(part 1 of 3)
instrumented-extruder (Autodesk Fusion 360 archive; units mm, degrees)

design "AS_Glue-Gun" references "AS_Hotend-Filsense", "AS_Hotend-Extruder", "AS_Hotend-Circuits", "AS_Hotend-Loadcell-Nozzle", "AS_Tool-Blank"
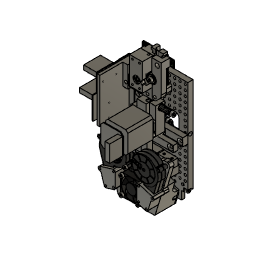
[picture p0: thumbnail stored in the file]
component_insert "Component Insert1"
joint "Assemble1" alignAngle 0 alignOffsetX 0 alignOffsetY 0 alignOffsetZ 0
component_insert "Component Insert2"
joint "Assemble2" alignAngle 0 alignOffsetX 0 alignOffsetY 0 alignOffsetZ 0
component_insert "Component Insert4"
joint "Assemble3" alignAngle 0 alignOffsetX 0 alignOffsetY 0 alignOffsetZ 0
component_insert "Component Insert13"
joint "Assemble6" alignAngle 0 alignOffsetX 0 alignOffsetY 0 alignOffsetZ 0
component_insert "Component Insert16"
joint "Assemble7" alignAngle -90 alignOffsetX 0 alignOffsetY 0 alignOffsetZ 0
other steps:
joint_origin "JointOrigin1"

design "PP_TRNS_Bondtech-Mini-Gears"
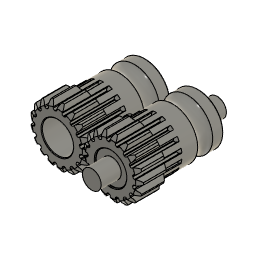
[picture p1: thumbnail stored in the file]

design "HW_M4x16-SHCS"
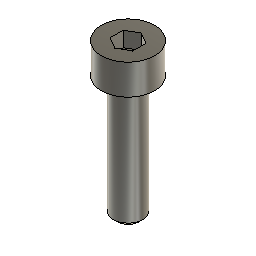
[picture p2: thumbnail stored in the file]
sketch "Sketch1" plane through (0, 0, 0) normal (0, 1, 0) x axis (1, 0, 0)
  line L1 (0, 16) -> (0, -4)
  line L2 (1.45, 16) -> (0, 16)
  line L3 (1.95, 15.5) -> (1.45, 16)
  line L4 (1.95, 0) -> (1.95, 15.5)
  line L5 (3.5, 0) -> (1.95, 0)
  line L6 (3.5, -4) -> (3.5, 0)
  line L7 (0, -4) -> (3.5, -4)
  point P1 (0, 0)
  point P4 (1.45, 16)
  point P5 (1.95, 15.5)
  point P3 (0, 16)
  point P7 (3.5, 0)
  point P8 (3.5, -4)
  point P2 (0, -4)
  vertical L1
  perpendicular L1 L2
  perpendicular L2 L4
  perpendicular L4 L5
  perpendicular L5 L6
  horizontal L7
  coincident P1 L1
  coincident P1 L5
  dimension "d1" distance P1 L2 = 16
  dimension "d2" angle L2 L3 = 45
  dimension "d3" distance P4 P5 = 0.5
  dimension "d4" distance P3 L4 = 1.95 (= "( 3.9 / 2 ) * 1 mm")
  dimension "d5" distance P7 P8 = 4
  dimension "d6" distance P2 P8 = 3.5 (= "( 7 / 2 ) * 1 mm")
revolve "Revolve1" sketch "Sketch1" AlongAngle 360
sketch "Sketch2" plane through (0, 0, 4) normal (0, 0, 1) x axis (-1, 0, 0)
  line L1 (0, -1.7321) -> (-1.5, -0.866)
  line L2 (1.5, -0.866) -> (0, -1.7321)
  line L3 (1.5, 0.866) -> (1.5, -0.866)
  line L4 (0, 1.7321) -> (1.5, 0.866)
  line L5 (-1.5, 0.866) -> (0, 1.7321)
  line L6 (-1.5, -0.866) -> (-1.5, 0.866)
  circle C1 centre (0, 0) radius 3.5
  point P1 (0, 0)
  point P9 (0, 0)
  point P5 (1.5, -0.866)
  coincident P1 P9
  vertical L6
  dimension "d8" distance P5 L6 = 3
extrude "Extrude1" cut sketch "Sketch2" profile of L1 L2 L3 L4 L5 L6 against normal blind 2

design "PP_OUTP_Dragon-Hotend"
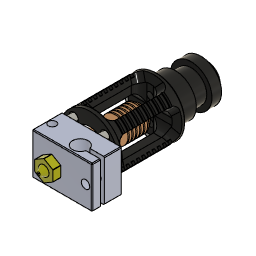
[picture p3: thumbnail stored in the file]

design "HW_M5x40-FHCS"
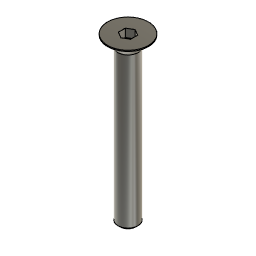
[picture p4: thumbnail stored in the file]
sketch "Sketch1" plane through (0, 0, 0) normal (0, 1, 0) x axis (1, 0, 0)
  line L1 (0, 40) -> (0, 0)
  line L2 (1.95, 40) -> (0, 40)
  line L3 (2.45, 39.5) -> (1.95, 40)
  line L4 (2.45, 2.8) -> (2.45, 39.5)
  line L5 (5, 0.25) -> (2.45, 2.8)
  line L6 (5, 0) -> (5, 0.25)
  line L7 (0, 0) -> (5, 0)
  point P1 (0, 0)
  point P2 (0, 0)
  point P9 (0, 0)
  point P3 (0, 40)
  point P4 (1.95, 40)
  point P8 (5, 0)
  point P7 (5, 0.25)
  coincident P1 P2
  vertical L1
  perpendicular L1 L2
  perpendicular L2 L4
  parallel L3 L5
  parallel L4 L6
  perpendicular L6 L7
  coincident P1 P9
  dimension "d1" distance P3 L4 = 2.45 (= "( 4.9 / 2 ) * 1 mm")
  dimension "d3" angle L2 L3 = 45
  dimension "d5" distance P4 L4 = 0.5
  dimension "d6" distance P2 P3 = 40
  dimension "d7" distance P8 P9 = 5 (= "( 10 / 2 ) * 1 mm")
  dimension "d9" distance P7 P8 = 0.25
revolve "Revolve1" sketch "Sketch1" AlongAngle 360
sketch "Sketch2" plane through (0, 0, 0) normal (0, 0, 1) x axis (-1, 0, 0)
  line L1 (0, -1.7321) -> (-1.5, -0.866)
  line L2 (1.5, -0.866) -> (0, -1.7321)
  line L3 (1.5, 0.866) -> (1.5, -0.866)
  line L4 (0, 1.7321) -> (1.5, 0.866)
  line L5 (-1.5, 0.866) -> (0, 1.7321)
  line L6 (-1.5, -0.866) -> (-1.5, 0.866)
  circle C1 centre (0, 0) radius 5
  point P1 (0, 0)
  point P9 (0, 0)
  coincident P1 P9
  vertical L6
  dimension "d12" distance L3 L6 = 3
extrude "Extrude1" cut sketch "Sketch2" profile of L1 L2 L3 L4 L5 L6 against normal blind 2

design "PP_ACTU_N17-Stepper" references "Fab Step"
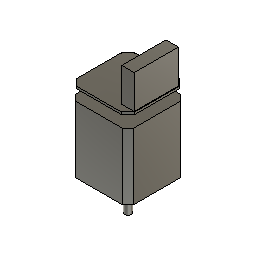
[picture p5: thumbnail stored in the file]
description: Nema 17 Stepper, 48mm Length Preferred, 5mm Shaft
sketch "Sketch1" plane through (0, 0, 0) normal (0, 0, 1) x axis (1, 0, 0)
  line L1 (-21.15, 21.15) -> (21.15, 21.15)
  line L2 (-21.15, -21.15) -> (-21.15, 21.15)
  line L3 (21.15, -21.15) -> (-21.15, -21.15)
  line L4 (21.15, 21.15) -> (21.15, -21.15)
  line L5 (-21.15, -21.15) -> (21.15, 21.15)
  line L6 (21.15, -21.15) -> (-21.15, 21.15)
  line L7 (15.5, 15.5) -> (-15.5, 15.5)
  line L8 (15.5, -15.5) -> (15.5, 15.5)
  line L9 (-15.5, -15.5) -> (15.5, -15.5)
  line L10 (-15.5, 15.5) -> (-15.5, -15.5)
  circle C1 centre (0, 0) radius 11
  circle C2 centre (-15.5, 15.5) radius 1.5
  circle C3 centre (-15.5, -15.5) radius 1.5
  circle C4 centre (15.5, -15.5) radius 1.5
  circle C5 centre (15.5, 15.5) radius 1.5
  circle C6 centre (0, 0) radius 2.5
  point P6 (0, 0)
  point P1 (0, 0)
  point P7 (0, 0)
  point P10 (15.5, -15.5)
  point P8 (-15.5, 15.5)
  point P9 (15.5, 15.5)
  point P12 (-15.5, 15.5)
  point P11 (-15.5, -15.5)
  point P13 (-15.5, -15.5)
  point P14 (15.5, -15.5)
  point P15 (15.5, 15.5)
  point P2 (21.15, 21.15)
  point P3 (-21.15, 21.15)
  perpendicular L1 L2
  parallel L1 L3
  parallel L2 L4
  horizontal L1
  coincident L5 P6
  coincident L6 P6
  coincident P1 P6
  equal L1 L2
  coincident P6 P7
  horizontal L7
  vertical L8
  horizontal L9
  vertical L10
  coincident L6 P10
  coincident L6 P8
  coincident L5 P9
  coincident P8 P12
  coincident P11 P13
  coincident P10 P14
  coincident P9 P15
  equal C2 C5
  equal C2 C3
  equal C2 C4
  concentric C1 C6
  dimension "d1" distance P2 P3 = 42.3
  dimension "d2" diameter C1 = 22
  dimension "d3" distance P8 P9 = 31
  dimension "d4" diameter C2 = 3
  dimension "d5" diameter C6 = 5
extrude "Extrude1" new body sketch "Sketch1" profile of L1 L2 L3 L4 C1 C2 C3 C4 C5 C6 along normal blind 48
extrude "Extrude2" cut sketch "Sketch1" profile of C2 C3 C4 C5 along normal blind 5
extrude "Extrude3" add sketch "Sketch1" profile of C1 C6 against normal blind 2
extrude "Extrude4" add sketch "Sketch1" profile of C6 against normal blind 24
chamfer "Chamfer1" distance 4
component_insert "Component Insert"
joint "Assemble1" alignAngle 0 alignOffsetX 0 alignOffsetY 0 alignOffsetZ 8
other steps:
joint_origin "JointOrigin1"

design "PP_FANS_40mm"
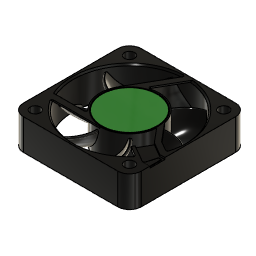
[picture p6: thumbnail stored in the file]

design "AS_Hotend-Filsense-Shaft" references "PP_BRNG_625-5x16x5", "PP_MAGU_2p5x8-469-1076-ND", "PP_SHFT_5x28-91585A562", "PP_TRNS_Bondtech-Single"
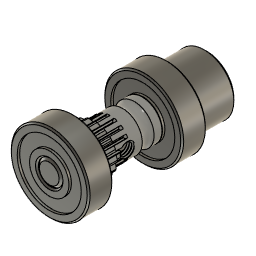
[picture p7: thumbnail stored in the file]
component_insert "Component Insert1"
component_insert "Component Insert3"
component_insert "Component Insert4"
component_insert "Component Insert5"
joint "Assemble1" alignAngle 0 alignOffsetX 0 alignOffsetY 0 alignOffsetZ 0
joint "Assemble2" alignAngle 0 alignOffsetX 0 alignOffsetY 0 alignOffsetZ 0
joint "Assemble3" alignAngle 0 alignOffsetX 0 alignOffsetY 0 alignOffsetZ 0
joint "Assemble4" alignAngle 0 alignOffsetX 0 alignOffsetY 0 alignOffsetZ 0
sketch "Sketch1" plane through (0, 0, 0) normal (1, 0, 0) x axis (0, 1, 0)
  line L1 (24, 2.45) -> (24, 6)
  line L2 (28, 2.45) -> (24, 2.45)
  line L3 (28, 0) -> (28, 2.45)
  line L4 (29.5, 0) -> (28, 0)
  line L5 (29.5, 4) -> (29.5, 0)
  line L6 (32, 4) -> (29.5, 4)
  line L7 (32, 6) -> (32, 4)
  line L8 (24, 6) -> (32, 6)
  point P2 (24, 6)
  point P10 (24, 6)
  point P1 (0, 0)
  point P4 (28, 2.45)
  point P5 (28, 0)
  point P3 (24, 2.45)
  point P6 (29.5, 0)
  point P7 (29.5, 4)
  point P8 (32, 4)
  vertical L1
  perpendicular L1 L2
  perpendicular L2 L3
  perpendicular L3 L4
  perpendicular L4 L5
  perpendicular L5 L6
  perpendicular L6 L7
  perpendicular L7 L8
  coincident P2 P10
  coincident P1 L4
  dimension "d17" distance P4 P5 = 2.45
  dimension "d18" distance P1 L3 = 28
  dimension "d19" distance P3 P4 = 4
  dimension "d20" distance P5 P6 = 1.5
  dimension "d21" distance P6 L6 = 4 (= "( 8 / 2 ) * 1 mm")
  dimension "d22" distance P7 P8 = 2.5
  dimension "d23" distance P6 L8 = 6
revolve "Revolve1" sketch "Sketch1" AlongAngle 360 bodies "FilsenseMagHold"
chamfer "Chamfer1" distance 0.5
chamfer "Chamfer2" distance 0.4
component_insert "Component Insert7"
joint "Assemble6" alignAngle 0 alignOffsetX 0 alignOffsetY 0 alignOffsetZ 0
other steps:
joint_origin "JointOrigin1"
joint_origin "JointOrigin3"
named bodies: "FilsenseMagHold"

design "HW_M5x08-BHCS"
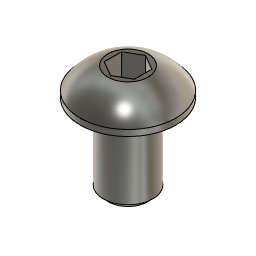
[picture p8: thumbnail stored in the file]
sketch "Sketch1" plane through (0, 0, 0) normal (0, 1, 0) x axis (1, 0, 0)
  line L1 (0, 8) -> (0, -2.75)
  line L2 (1.95, 8) -> (0, 8)
  line L3 (2.45, 7.5) -> (1.95, 8)
  line L4 (2.45, 0) -> (2.45, 7.5)
  line L5 (4.75, 0) -> (2.45, 0)
  line L6 (4.75, -0.6) -> (4.75, 0)
  line L7 (2, -2.75) -> (0, -2.75)
  arc A1 centre (0, 2.6419) radius 5.7508 clockwise from (4.75, -0.6) to (2, -2.75)
  point P1 (0, 0)
  point P10 (0, 2.6419)
  point P3 (0, 8)
  point P2 (0, -2.75)
  point P9 (2, -2.75)
  point P7 (4.75, 0)
  point P8 (4.75, -0.6)
  point P5 (2.45, 7.5)
  vertical L1
  perpendicular L1 L2
  perpendicular L2 L4
  perpendicular L4 L5
  perpendicular L5 L6
  perpendicular L1 L7
  coincident P1 L5
  coincident L1 P10
  coincident P1 L1
  dimension "d1" distance P1 P3 = 8
  dimension "d2" distance P1 P2 = 2.75
  dimension "d3" distance P2 P9 = 2 (= "( 4 / 2 ) * 1 mm")
  dimension "d4" distance P7 P8 = 0.6
  dimension "d5" distance L1 P7 = 4.75 (= "( 9.5 / 2 ) * 1 mm")
  dimension "d6" distance P1 L4 = 2.45 (= "( 4.9 / 2 ) * 1 mm")
  dimension "d7" angle L2 L3 = 45
  dimension "d8" distance L2 P5 = 0.5
revolve "Revolve1" sketch "Sketch1" AlongAngle 360
sketch "Sketch2" plane through (0, 0, 2.75) normal (0, 0, 1) x axis (-1, 0, 0)
  line L1 (0, -1.7321) -> (-1.5, -0.866)
  line L2 (1.5, -0.866) -> (0, -1.7321)
  line L3 (1.5, 0.866) -> (1.5, -0.866)
  line L4 (0, 1.7321) -> (1.5, 0.866)
  line L5 (-1.5, 0.866) -> (0, 1.7321)
  line L6 (-1.5, -0.866) -> (-1.5, 0.866)
  circle C1 centre (0, 0) radius 2
  point P2 (0, 0)
  point P9 (0, 0)
  point P5 (1.5, -0.866)
  coincident P2 P9
  vertical L3
  dimension "d10" distance P5 L6 = 3
extrude "Extrude1" cut sketch "Sketch2" profile of L1 L2 L3 L4 L5 L6 to an object offset 0.5

design "HW_M5x10-SHCS"
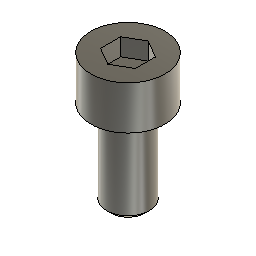
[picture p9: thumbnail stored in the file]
sketch "Sketch1" plane through (0, 0, 0) normal (0, 1, 0) x axis (1, 0, 0)
  line L1 (0, 10) -> (0, -5)
  line L2 (1.95, 10) -> (0, 10)
  line L3 (2.45, 9.5) -> (1.95, 10)
  line L4 (2.45, 0) -> (2.45, 9.5)
  line L5 (4.25, 0) -> (2.45, 0)
  line L6 (4.25, -5) -> (4.25, 0)
  line L7 (0, -5) -> (4.25, -5)
  point P1 (0, 0)
  point P4 (1.95, 10)
  point P5 (2.45, 9.5)
  point P3 (0, 10)
  point P7 (4.25, 0)
  point P8 (4.25, -5)
  point P2 (0, -5)
  vertical L1
  perpendicular L1 L2
  perpendicular L2 L4
  perpendicular L4 L5
  perpendicular L5 L6
  horizontal L7
  coincident P1 L1
  coincident P1 L5
  dimension "d1" distance P1 L2 = 10
  dimension "d2" angle L2 L3 = 45
  dimension "d3" distance P4 P5 = 0.5
  dimension "d4" distance P3 L4 = 2.45 (= "( 4.9 / 2 ) * 1 mm")
  dimension "d5" distance P7 P8 = 5
  dimension "d6" distance P2 P8 = 4.25 (= "( 8.5 / 2 ) * 1 mm")
revolve "Revolve1" sketch "Sketch1" AlongAngle 360
sketch "Sketch2" plane through (0, 0, 5) normal (0, 0, 1) x axis (-1, 0, 0)
  line L1 (0, -2.3094) -> (-2, -1.1547)
  line L2 (2, -1.1547) -> (0, -2.3094)
  line L3 (2, 1.1547) -> (2, -1.1547)
  line L4 (0, 2.3094) -> (2, 1.1547)
  line L5 (-2, 1.1547) -> (0, 2.3094)
  line L6 (-2, -1.1547) -> (-2, 1.1547)
  circle C1 centre (0, 0) radius 4.25
  point P1 (0, 0)
  point P9 (0, 0)
  point P5 (2, -1.1547)
  coincident P1 P9
  vertical L6
  dimension "d8" distance P5 L6 = 4
extrude "Extrude1" cut sketch "Sketch2" profile of L1 L2 L3 L4 L5 L6 against normal blind 2

design "PP_FANS_505015"
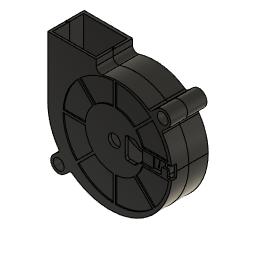
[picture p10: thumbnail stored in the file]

design "PP_SENS_Loadcell-80mm"
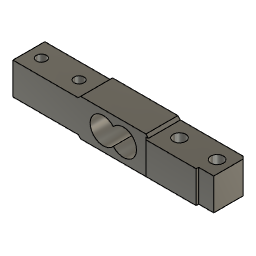
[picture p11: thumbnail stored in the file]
sketch "Sketch1" plane through (0, 0, 0) normal (0, 0, 1) x axis (1, 0, 0)
  line L1 (80, 0) -> (0, 0)
  line L2 (80, -12.7) -> (80, 0)
  line L3 (0, -12.7) -> (80, -12.7)
  line L4 (0, 0) -> (0, -12.7)
  line L5 (80, -6.35) -> (0, -6.35)
  line L6 (40, -12.7) -> (40, 0)
  line L7 (26, -12.7) -> (26, 0)
  line L8 (54, -12.7) -> (54, 0)
  circle C1 centre (5, -6.35) radius 2
  circle C2 centre (20, -6.35) radius 2
  circle C3 centre (60, -6.35) radius 2.5
  circle C4 centre (75, -6.35) radius 2.5
  point P1 (0, 0)
  point P2 (0, 0)
  point P6 (0, -6.35)
  point P7 (80, -6.35)
  point P8 (5, -6.35)
  point P9 (20, -6.35)
  point P10 (60, -6.35)
  point P11 (75, -6.35)
  point P12 (40, 0)
  point P13 (40, -12.7)
  point P14 (26, 0)
  point P15 (26, -12.7)
  point P16 (54, 0)
  point P17 (54, -12.7)
  point P3 (80, 0)
  point P5 (0, -12.7)
  horizontal L1
  vertical L2
  horizontal L3
  vertical L4
  coincident P1 P2
  midpoint L4 P6
  midpoint L2 P7
  coincident L5 P8
  coincident L5 P9
  coincident L5 P10
  coincident L5 P11
  midpoint L1 P12
  midpoint L3 P13
  equal C1 C2
  equal C3 C4
  coincident L1 P14
  coincident L3 P15
  perpendicular L3 L7
  coincident L1 P16
  coincident L3 P17
  perpendicular L3 L8
  dimension "d1" distance P2 P3 = 80
  dimension "d2" distance P9 L6 = 20
  dimension "d3" distance P8 P9 = 15
  dimension "d4" diameter C1 = 4
  dimension "d5" distance P2 P5 = 12.7
  dimension "d6" distance P10 P11 = 15 (= "d3")
  dimension "d7" distance P10 L6 = 20 (= "d2")
  dimension "d8" diameter C3 = 5
  dimension "d15" distance P10 L8 = 6
  dimension "d16" distance P9 L7 = 6
extrude "Extrude1" new body sketch "Sketch1" profile of L1 L2 L3 L4 C1 C2 C3 C4 along normal blind 12.7
sketch "Sketch2" plane through (0, -12.7, 0) normal (0, -1, 0) x axis (1, 0, 0)
  line L1 (80, 0) -> (0, 0)
  line L2 (80, 12.7) -> (80, 0)
  line L3 (0, 12.7) -> (80, 12.7)
  line L4 (0, 0) -> (0, 12.7)
  line L5 (40, 0) -> (40, 12.7)
  line L6 (44, 6.35) -> (36, 6.35)
  circle C1 centre (36, 6.35) radius 5.25
  circle C2 centre (44, 6.35) radius 5.25
  point P6 (40, 12.7)
  point P7 (40, 0)
  point P8 (36, 6.35)
  point P10 (36, 6.35)
  point P9 (44, 6.35)
  point P11 (44, 6.35)
  midpoint L3 P6
  midpoint L1 P7
  perpendicular L5 L6
  midpoint L5 L6
  coincident P8 P10
  coincident P9 P11
  equal C1 C2
  dimension "d11" diameter C1 = 10.5
  dimension "d12" distance P8 P9 = 8
extrude "Extrude2" cut sketch "Sketch2" profile of C1 C2 to an object
extrude "Extrude3" add sketch "Sketch1" profile of L1 L3 L7 L8 against normal blind 1
extrude "Extrude4" sketch "Sketch1" profile of L1 L3 L7 L8 blind 1
sketch "Sketch3" plane through (0, -12.7, 0) normal (0, -1, 0) x axis (1, 0, 0)
  line L1 (80, 0) -> (54, 0)
  line L2 (80, 12.7) -> (80, 0)
  line L3 (54, 12.7) -> (80, 12.7)
  line L4 (54, 13.7) -> (54, 12.7)
  line L5 (26, 13.7) -> (54, 13.7)
  line L6 (26, 12.7) -> (26, 13.7)
  line L7 (0, 12.7) -> (26, 12.7)
  line L8 (0, 0) -> (0, 12.7)
  line L9 (26, 0) -> (0, 0)
  line L10 (26, -1) -> (26, 0)
  line L11 (54, -1) -> (26, -1)
  line L12 (54, 0) -> (54, -1)
  line L13 (54, 0) -> (54, 12.7)
  line L14 (74, 0) -> (74, 12.7)
  arc A1 centre (36, 6.35) radius 5.25 clockwise from (40, 2.9496) to (40, 9.7504)
  arc A2 centre (44, 6.35) radius 5.25 clockwise from (40, 9.7504) to (40, 2.9496)
  point P18 (54, 12.7)
  point P19 (54, 0)
  point P20 (74, 12.7)
  point P21 (74, 0)
  point P9 (54, 12.7)
  coincident L3 P18
  coincident L1 P19
  perpendicular L1 L13
  coincident L3 P20
  coincident L1 P21
  perpendicular L1 L14
  coincident P9 L13
  dimension "d22" distance L2 L14 = 6
extrude "Extrude5" add sketch "Sketch3" profile of L1 L3 L13 L14 along normal blind 1
chamfer "Chamfer1" distance 1
chamfer "Chamfer2" distance 1

design "HW_M4x20-SHCS"
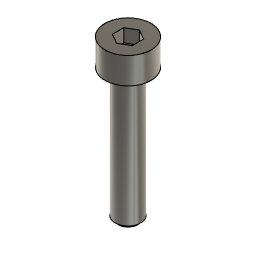
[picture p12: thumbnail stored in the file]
sketch "Sketch1" plane through (0, 0, 0) normal (0, 1, 0) x axis (1, 0, 0)
  line L1 (0, 20) -> (0, -4)
  line L2 (1.45, 20) -> (0, 20)
  line L3 (1.95, 19.5) -> (1.45, 20)
  line L4 (1.95, 0) -> (1.95, 19.5)
  line L5 (3.5, 0) -> (1.95, 0)
  line L6 (3.5, -4) -> (3.5, 0)
  line L7 (0, -4) -> (3.5, -4)
  point P1 (0, 0)
  point P4 (1.45, 20)
  point P5 (1.95, 19.5)
  point P3 (0, 20)
  point P7 (3.5, 0)
  point P8 (3.5, -4)
  point P2 (0, -4)
  vertical L1
  perpendicular L1 L2
  perpendicular L2 L4
  perpendicular L4 L5
  perpendicular L5 L6
  horizontal L7
  coincident P1 L1
  coincident P1 L5
  dimension "d1" distance P1 L2 = 20
  dimension "d2" angle L2 L3 = 45
  dimension "d3" distance P4 P5 = 0.5
  dimension "d4" distance P3 L4 = 1.95 (= "( 3.9 / 2 ) * 1 mm")
  dimension "d5" distance P7 P8 = 4
  dimension "d6" distance P2 P8 = 3.5 (= "( 7 / 2 ) * 1 mm")
revolve "Revolve1" sketch "Sketch1" AlongAngle 360
sketch "Sketch2" plane through (0, 0, 4) normal (0, 0, 1) x axis (-1, 0, 0)
  line L1 (0, -1.7321) -> (-1.5, -0.866)
  line L2 (1.5, -0.866) -> (0, -1.7321)
  line L3 (1.5, 0.866) -> (1.5, -0.866)
  line L4 (0, 1.7321) -> (1.5, 0.866)
  line L5 (-1.5, 0.866) -> (0, 1.7321)
  line L6 (-1.5, -0.866) -> (-1.5, 0.866)
  circle C1 centre (0, 0) radius 3.5
  point P1 (0, 0)
  point P9 (0, 0)
  point P5 (1.5, -0.866)
  coincident P1 P9
  vertical L6
  dimension "d8" distance P5 L6 = 3
extrude "Extrude1" cut sketch "Sketch2" profile of L1 L2 L3 L4 L5 L6 against normal blind 2

design "HW_M3x8-FHCS"
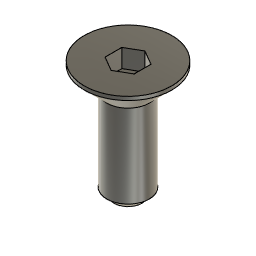
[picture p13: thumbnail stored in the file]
sketch "Sketch1" plane through (0, 0, 0) normal (0, 1, 0) x axis (1, 0, 0)
  line L1 (0, 8) -> (0, 0)
  line L2 (0.95, 8) -> (0, 8)
  line L3 (1.45, 7.5) -> (0.95, 8)
  line L4 (1.45, 1.8) -> (1.45, 7.5)
  line L5 (3, 0.25) -> (1.45, 1.8)
  line L6 (3, 0) -> (3, 0.25)
  line L7 (0, 0) -> (3, 0)
  point P1 (0, 0)
  point P2 (0, 0)
  point P9 (0, 0)
  point P3 (0, 8)
  point P4 (0.95, 8)
  point P8 (3, 0)
  point P7 (3, 0.25)
  coincident P1 P2
  vertical L1
  perpendicular L1 L2
  perpendicular L2 L4
  parallel L3 L5
  parallel L4 L6
  perpendicular L6 L7
  coincident P1 P9
  dimension "d1" distance P3 L4 = 1.45 (= "( 2.9 / 2 ) * 1 mm")
  dimension "d3" angle L2 L3 = 45
  dimension "d5" distance P4 L4 = 0.5
  dimension "d6" distance P2 P3 = 8
  dimension "d7" distance P8 P9 = 3 (= "( 6 / 2 ) * 1 mm")
  dimension "d9" distance P7 P8 = 0.25
revolve "Revolve1" sketch "Sketch1" AlongAngle 360
sketch "Sketch2" plane through (0, 0, 0) normal (0, 0, 1) x axis (-1, 0, 0)
  line L1 (0, -1.1547) -> (-1, -0.5774)
  line L2 (1, -0.5774) -> (0, -1.1547)
  line L3 (1, 0.5774) -> (1, -0.5774)
  line L4 (0, 1.1547) -> (1, 0.5774)
  line L5 (-1, 0.5774) -> (0, 1.1547)
  line L6 (-1, -0.5774) -> (-1, 0.5774)
  circle C1 centre (0, 0) radius 3
  point P1 (0, 0)
  point P9 (0, 0)
  coincident P1 P9
  vertical L6
  dimension "d12" distance L3 L6 = 2
extrude "Extrude1" cut sketch "Sketch2" profile of L1 L2 L3 L4 L5 L6 against normal blind 1.26

design "AS_Hotend-Loadcell-Nozzle" references "HW_M4x16-SHCS", "HW_M4x20-SHCS", "PP_SENS_Loadcell-80mm", "HW_M3x8-FHCS", "PP_FANS_40mm", "PP_FANS_505015", "HW_M5x40-FHCS", "PP_OUTP_Dragon-Hotend", "HW_M4x25-FHCS"
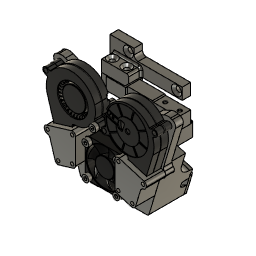
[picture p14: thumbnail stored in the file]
parameter "d152" = 8
parameter "d223" = 7
parameter "d317" = 2.5
sketch "Plan" plane through (0, 0, 0) normal (0, 0, 1) x axis (1, 0, 0)
  line L1 (-40, 3.65) -> (40, 3.65)
  line L2 (-40, 16.35) -> (-40, 3.65)
  line L3 (40, 16.35) -> (-40, 16.35)
  line L4 (40, 3.65) -> (40, 16.35)
  line L5 (15.5, 10) -> (40, 10)
  line L6 (15.5, 3.65) -> (15.5, 16.35)
  line L7 (-20, 0.25) -> (-20, 16.35)
  line L8 (40, 0.25) -> (-20, 0.25)
  line L9 (40, 3.65) -> (40, 0.25)
  line L10 (15.5, 1.65) -> (15.5, 3.65)
  line L11 (40, 1.65) -> (15.5, 1.65)
  line L12 (20, -0.25) -> (-20, -0.25)
  line L13 (20, -22.65) -> (20, -0.25)
  line L14 (-20, -22.65) -> (20, -22.65)
  line L15 (-20, -0.25) -> (-20, -22.65)
  line L16 (-20, 18.35) -> (-20, 16.35)
  line L17 (40, 18.35) -> (-20, 18.35)
  line L18 (40, 16.35) -> (40, 18.35)
  line L19 (15.5, 18.35) -> (15.5, 16.35)
  line L20 (15.5, 0.25) -> (15.5, 1.65)
  circle C1 centre (0, 0) radius 6
  circle C2 centre (0, 0) radius 8
  circle C3 centre (0, 0) radius 11.25
  circle C4 centre (20, 10) radius 2.125
  circle C5 centre (35, 10) radius 2.125
  point P1 (0, 0)
  point P2 (0, 0)
  point P3 (0, 0)
  point P9 (40, 10)
  point P11 (15.5, 16.35)
  point P12 (15.5, 3.65)
  point P10 (15.5, 10)
  point P13 (20, 10)
  point P14 (35, 10)
  point P15 (-20, 16.35)
  point P5 (40, 3.65)
  point P18 (40, 3.65)
  point P20 (40, 1.65)
  point P27 (40, 16.35)
  point P8 (40, 16.35)
  point P28 (15.5, 18.35)
  point P29 (15.5, 0.25)
  point P7 (-40, 16.35)
  point P4 (0, 0)
  point P6 (-40, 3.65)
  point P19 (15.5, 1.65)
  point P21 (-20, -0.25)
  point P24 (-20, -22.65)
  point P25 (-20, 18.35)
  coincident P1 P2
  coincident P1 P3
  concentric C1 C3
  horizontal L1
  vertical L2
  horizontal L3
  vertical L4
  midpoint L4 P9
  perpendicular L4 L5
  coincident L3 P11
  coincident L1 P12
  perpendicular L1 L6
  coincident P10 L6
  coincident L5 P13
  coincident L5 P14
  equal C4 C5
  coincident L3 P15
  perpendicular L3 L7
  perpendicular L7 L8
  perpendicular L8 L9
  coincident P5 P18
  perpendicular L1 L10
  perpendicular L9 L11
  coincident L9 P20
  horizontal L12
  vertical L13
  horizontal L14
  vertical L15
  perpendicular L3 L16
  perpendicular L7 L17
  coincident L3 P27
  perpendicular L3 L18
  coincident P8 P27
  coincident L17 P28
  perpendicular L17 L19
  equal L10 L19
  coincident L8 P29
  perpendicular L8 L20
  dimension "d1" diameter C3 = 22.5
  dimension "d2" diameter C2 = 16
  dimension "d3" diameter C1 = 12
  dimension "d4" distance P7 P8 = 80
  dimension "d5" distance P5 P8 = 12.7
  dimension "d6" distance P9 P10 = 24.5
  dimension "d7" diameter C4 = 4.25
  dimension "d8" distance P13 P14 = 15
  dimension "d9" distance P9 P14 = 5
  dimension "d10" distance P4 L5 = 10
  dimension "d11" distance P4 P6 = 40
  dimension "d12" distance P4 L8 = 0.25
  dimension "d13" distance P12 P19 = 2
  dimension "d14" distance P4 L7 = 20
  dimension "d49" distance P4 L12 = 0.25 (= "d12")
  dimension "d50" distance P4 L15 = 20
  dimension "d51" distance P4 L13 = 20
  dimension "d52" distance P21 P24 = 22.4
  dimension "d84" distance L14 P25 = 41
extrude "Extrude1" new body sketch "Plan" profile of C1 C2 C3 L1 L3 L4 L6 C4 C5 L7 L8 L9 L10 L11 L12 L13 L14 L15 L16 L17 L18 L19 along normal blind 6
extrude "Extrude2" sketch "Plan" profile of C2 C3 L1 L3 L4 L6 C4 C5 L7 L8 L9 L10 L11 L12 L13 L14 L15 L16 L17 L18 L19 blind 6.5
extrude "Extrude3" sketch "Plan" profile of L1 L3 L4 L6 C4 C5 L9 L10 L11 L17 L18 L19 blind 3
extrude "Extrude4" sketch "Plan" profile of L1 L3 L9 L10 L11 L17 L18 L19 blind 2
extrude "Extrude17" cut sketch "Plan" profile of L1 L3 L4 L6 C4 C5 L8 L9 L10 L11 L17 L18 L19 L20 along normal blind 2.5
chamfer "Chamfer1" distance 1
chamfer "Chamfer2" distance 0.5
chamfer "Chamfer3" distance 2.25
fillet "Fillet2" radius 2
chamfer "Chamfer8" distance 0.5
component_insert "Component Insert1"
joint "Assemble1" alignAngle 180 alignOffsetX 0 alignOffsetY 0 alignOffsetZ 0
component_insert "Component Insert3"
component_insert "Component Insert4"
joint "Assemble3" alignAngle 0 alignOffsetX 0 alignOffsetY 0 alignOffsetZ 0
joint "Assemble4" alignAngle 0 alignOffsetX 0 alignOffsetY 0 alignOffsetZ 0
component_insert "Component Insert5"
joint "Assemble5" alignAngle -90 alignOffsetX 0 alignOffsetY 0 alignOffsetZ 0
extrude "Extrude5" add sketch "Plan" profile of C2 C3 L12 L13 L14 L15 against normal blind 6.5
extrude "Extrude6" sketch "Plan" profile of C3 L12 L13 L14 L15 blind -26.5
sketch "Fan Face" plane through (0, -22.65, 0) normal (0, -1, 0) x axis (1, 0, 0)
  line L1 (20, 12.5) -> (20, -33)
  line L2 (-20, 12.5) -> (20, 12.5)
  line L3 (-20, -33) -> (-20, 12.5)
  line L4 (20, -33) -> (-20, -33)
  line L5 (12.5, 6.5) -> (-12.5, 6.5)
  line L6 (0, 6.5) -> (0, 0)
  line L7 (16, -3) -> (-16, -3)
  line L8 (16, -35) -> (16, -3)
  line L9 (-16, -35) -> (16, -35)
  line L10 (-16, -3) -> (-16, -35)
  line L11 (0, 0) -> (0, -3)
  line L12 (-20, -39) -> (-20, -33)
  line L13 (20, -39) -> (-20, -39)
  line L14 (20, -33) -> (20, -39)
  line L15 (16, -35) -> (-16, -3)
  line L16 (0, -52.5) -> (0, -39)
  line L17 (-23.3827, -39) -> (0, -52.5)
  line L18 (20, 1) -> (-20, 1)
  line L19 (-35.2971, -50) -> (-17.0566, -50)
  line L20 (-35.3503, -39.4381) -> (-17.0566, -50)
  line L21 (-46.6163, -2.0998) -> (-35.3503, -39.4381)
  line L22 (-14.75, -46.0048) -> (-20, -42.9737)
  line L23 (-14.75, -39) -> (-14.75, -46.0048)
  line L24 (-17.0566, -50) -> (-14.75, -46.0048)
  line L25 (-20, -39) -> (-20, -42.9737)
  line L26 (-35.2971, -50) -> (-49.4884, -2.9664)
  line L27 (-43.7111, -22.1138) -> (-20, -14.9595)
  line L28 (-38.0948, -30.3422) -> (-20, -24.8825)
  line L29 (-22.3066, -46.9689) -> (-20, -42.9737)
  line L30 (-29.3837, 3.0998) -> (-46.6163, -2.0998)
  line L31 (-49.4884, -2.9664) -> (-46.6163, -2.0998)
  line L32 (-28.187, 3.4609) -> (-29.3837, 3.0998)
  line L33 (-30.9143, 12.5) -> (-28.187, 3.4609)
  line L34 (-20, -28) -> (-29.3837, 3.0998)
  line L35 (-20, 12.5) -> (-30.9143, 12.5)
  line L36 (-22.0566, -50) -> (-38.0902, -40.743)
  line L37 (-51.3051, 3.0544) -> (-49.4884, -2.9664)
  line L38 (-30.0036, 9.4816) -> (-51.3051, 3.0544)
  line L39 (-20, 12.5) -> (-30.0036, 9.4816)
  line L40 (-4.2364, 18.4169) -> (-56.3806, 42.3756)
  line L41 (-4.2364, 18.4169) -> (-38, 0.5)
  line L42 (-38, 0.5) -> (-56.3806, 42.3756)
  line L43 (-64.625, 47.1998) -> (-51.3051, 3.0544)
  line L44 (-54.4201, 50.2789) -> (-64.625, 47.1998)
  line L45 (0, 28.4169) -> (0, 12.5)
  line L46 (-6.8393, 28.4169) -> (-54.4201, 50.2789)
  line L47 (0, 28.4169) -> (-6.8393, 28.4169)
  line L48 (-48.3908, -0.5461) -> (-47.813, -2.4609)
  line L49 (-20.5, 7.8693) -> (-50.0662, -1.0516)
  line L50 (-20.5, -25.5556) -> (-20.5, 7.8693)
  line L51 (-40.8225, -31.6875) -> (-20.5, -25.5556)
  line L52 (-53.8956, -2.2071) -> (-50.0662, -1.0516)
  line L53 (-51.8736, -8.9087) -> (-53.8956, -2.2071)
  line L54 (-48.0441, -7.7532) -> (-51.8736, -8.9087)
  line L55 (-28.6797, 29.6479) -> (-28.5753, 29.8751)
  circle C1 centre (-12.5, 6.5) radius 2.2
  circle C2 centre (-12.5, 6.5) radius 2.75
  circle C3 centre (12.5, 6.5) radius 2.2
  circle C4 centre (12.5, 6.5) radius 2.75
  circle C5 centre (-12.5, 6.5) radius 5.25
  circle C6 centre (16, -3) radius 1.75
  circle C7 centre (-16, -3) radius 1.75
  circle C8 centre (-16, -35) radius 1.75
  circle C9 centre (16, -35) radius 1.75
  circle C10 centre (0, -19) radius 16.5
  circle C11 centre (12.5, 6.5) radius 5.25
  circle C12 centre (-4.2364, 18.4169) radius 1.75
  circle C13 centre (-56.3806, 42.3756) radius 1.75
  circle C14 centre (-24, 3.1574) radius 1.35
  circle C15 centre (-24, 3.1574) radius 1.75
  circle C16 centre (-24, 3.1574) radius 3.5
  circle C17 centre (-24, -22.9558) radius 1.35
  circle C18 centre (-24, -22.9558) radius 1.75
  circle C19 centre (-24, -22.9558) radius 3.5
  circle C20 centre (-38.4827, -27.3257) radius 1.35
  circle C21 centre (-38.4827, -27.3257) radius 1.75
  circle C22 centre (-38.4827, -27.3257) radius 3.5
  circle C23 centre (-49.5338, -4.5469) radius 1.35
  circle C24 centre (-49.5338, -4.5469) radius 1.75
  circle C25 centre (-49.5338, -4.5469) radius 3.5
  circle C26 centre (-28.5753, 29.8751) radius 16.5
  point P1 (0, 0)
  point P8 (0, 0)
  point P9 (0, 6.5)
  point P6 (-12.5, 6.5)
  point P10 (-12.5, 6.5)
  point P7 (12.5, 6.5)
  point P12 (12.5, 6.5)
  point P16 (16, -3)
  point P19 (16, -3)
  point P15 (-16, -3)
  point P20 (-16, -3)
  point P18 (-16, -35)
  point P21 (-16, -35)
  point P17 (16, -35)
  point P22 (16, -35)
  point P23 (0, -3)
  point P24 (0, 0)
  point P5 (-20, -33)
  point P25 (-20, -33)
  point P2 (20, -33)
  point P28 (20, -33)
  point P30 (-16, -3)
  point P31 (16, -35)
  point P29 (0, -19)
  point P32 (0, -39)
  point P34 (-23.3827, -39)
  point P35 (-20, 1)
  point P36 (20, 1)
  point P45 (-14.75, -39)
  point P39 (-35.2971, -50)
  point P47 (-35.2971, -50)
  point P40 (-35.3503, -39.4381)
  point P41 (-35.3503, -39.4381)
  point P48 (-20, -14.9595)
  point P49 (-43.7111, -22.1138)
  point P50 (-20, -24.8825)
  point P51 (-38.0948, -30.3422)
  point P52 (-22.3066, -46.9689)
  point P57 (-20, -28)
  point P58 (-38, 0.5)
  point P4 (-20, 12.5)
  point P59 (-20, 12.5)
  point P60 (-38.0902, -40.743)
  point P61 (-22.0566, -50)
  point P46 (-49.4884, -2.9664)
  point P54 (-49.4884, -2.9664)
  point P63 (-30.0036, 9.4816)
  point P64 (-20, 12.5)
  point P66 (-56.3806, 42.3756)
  point P67 (-56.3806, 42.3756)
  point P65 (-4.2364, 18.4169)
  point P68 (-4.2364, 18.4169)
  point P69 (-38, 0.5)
  point P70 (-4.2364, 18.4169)
  point P71 (-56.3806, 42.3756)
  point P72 (-38, 0.5)
  point P74 (0, 12.5)
  point P78 (-47.813, -2.4609)
  point P80 (-50.0662, -1.0516)
  point P79 (-48.3908, -0.5461)
  point P92 (-40.8225, -31.6875)
  point P98 (-48.0441, -7.7532)
  point P99 (-28.5753, 29.8751)
  point P100 (-28.5753, 29.8751)
  point P101 (-28.6797, 29.6479)
  point P11 (-12.5, 6.5)
  point P27 (20, -39)
  point P33 (0, -52.5)
  point P26 (-20, -39)
  point P42 (-46.6163, -2.0998)
  point P53 (-29.3837, 3.0998)
  point P55 (-28.187, 3.4609)
  point P87 (-24, -22.9558)
  perpendicular L3 L5
  coincident P1 P8
  midpoint L5 P9
  vertical L6
  coincident P6 P10
  concentric C1 C2
  coincident P7 P12
  concentric C3 C4
  equal C1 C3
  equal C2 C4
  concentric C2 C5
  horizontal L7
  vertical L8
  horizontal L9
  vertical L10
  equal L7 L8
  equal C8 C9
  equal C7 C8
  equal C6 C7
  coincident P16 P19
  coincident P15 P20
  coincident P18 P21
  coincident P17 P22
  midpoint L7 P23
  coincident P1 P24
  vertical L11
  coincident P5 P25
  perpendicular L9 L12
  perpendicular L12 L13
  perpendicular L9 L14
  coincident P2 P28
  coincident P20 P30
  coincident P22 P31
  midpoint P29 L15
  midpoint L13 P32
  perpendicular L13 L16
  coincident L13 P34
  coincident L3 P35
  coincident L1 P36
  perpendicular L1 L18
  concentric C4 C11
  equal C5 C11
  horizontal L19
  vertical L23
  coincident L13 P45
  parallel L17 L22
  parallel L17 L20
  perpendicular L22 L24
  coincident P39 P47
  vertical L25
  coincident P40 P41
  coincident L3 P48
  coincident L26 P49
  coincident L3 P50
  coincident L21 P51
  coincident L20 P52
  perpendicular L20 L29
  parallel L21 L26
  perpendicular L21 L30
  perpendicular L21 L31
  parallel L30 L32
  perpendicular L30 L33
  perpendicular L30 L34
  coincident L3 P57
  midpoint L30 P58
  coincident P4 P59
  horizontal L35
  coincident L26 P60
  coincident L19 P61
  parallel L20 L36
  coincident P46 P54
  perpendicular L31 L37
  coincident L33 P63
  perpendicular L33 L38
  coincident L3 P64
  perpendicular L33 L39
  perpendicular L21 L27
  coincident P59 P64
  coincident P66 P67
  coincident P65 P68
  coincident P58 P69
  coincident P65 P70
  coincident P66 P71
  coincident P58 P72
  equal C12 C13
  perpendicular L38 L43
  perpendicular L37 L44
  midpoint L2 P74
  perpendicular L2 L45
  perpendicular L45 L47
  parallel L40 L46
  coincident L31 P78
  perpendicular L31 L48
  coincident L37 P80
  parallel L30 L49
  coincident P79 L49
  concentric C14 C15
  concentric C14 C16
  vertical L50
  tangent C16 L50
  tangent L49 C16
  concentric C17 C18
  equal C14 C17
  equal C15 C18
  concentric C18 C19
  equal C16 C19
  tangent L50 C19
  concentric C20 C21
  concentric C20 C22
  equal C16 C22
  equal C14 C20
  equal C15 C21
  coincident L26 P92
  perpendicular L26 L51
  tangent C19 L51
  tangent C22 L51
  tangent L26 C22
  parallel L27 L28
  concentric C23 C24
  concentric C24 C25
  equal C16 C25
  equal C15 C24
  equal C14 C23
  tangent L21 C25
  tangent L49 C25
  perpendicular L37 L52
  perpendicular L52 L53
  coincident L26 P98
  perpendicular L26 L54
  tangent C25 L53
  tangent C25 L54
  coincident P99 P100
  coincident L40 P101
  perpendicular L40 L55
  dimension "d62" diameter C1 = 4.4
  dimension "d63" diameter C2 = 5.5
  dimension "d65" diameter C5 = 10.5
  dimension "d66" distance P6 P7 = 25
  dimension "d67" distance P1 L5 = 6.5
  dimension "d68" distance L2 P11 = 6
  dimension "d69" distance L3 P11 = 7.5
  dimension "d85" distance P15 P16 = 32
  dimension "d86" diameter C7 = 3.5
  dimension "d88" distance L9 P27 = 4
  dimension "d89" diameter C10 = 33
  dimension "d206" angle L16 L17 = 60
  dimension "d240" distance P1 L7 = 3
  dimension "d305" distance P20 L18 = 4 (= "d88")
  dimension "d306" distance P1 P33 = 52.5
  dimension "d307" distance P33 L19 = 2.5
  dimension "d312" distance L17 L22 = 1.75
  dimension "d313" distance L20 L22 = 4.6132
  dimension "d319" distance P26 L23 = 5.25
  dimension "d344" distance P42 P53 = 18
  dimension "d345" distance L26 P51 = 3
  dimension "d346" distance P53 P55 = 1.25
  dimension "d347" angle L12 L21 = 16.79
  dimension "d349" distance L2 P58 = 12
  dimension "d354" distance P41 L36 = 2.5
  dimension "d357" distance P25 P57 = 5
  dimension "d363" distance P42 L27 = 20
  dimension "d370" distance P67 P68 = 57.385
  dimension "d371" distance P69 P70 = 38.223
  dimension "d372" distance P71 P72 = 45.732
  dimension "d373" diameter C13 = 3.5
  dimension "d374" distance L30 P65 = 7.4
  dimension "d375" distance P9 P58 = 38
  dimension "d376" distance P66 L44 = 7
  dimension "d382" distance P65 L47 = 10
  dimension "d383" distance P66 L46 = 8
  dimension "d384" distance P42 L48 = 1.25
  dimension "d385" diameter C14 = 2.7
  dimension "d386" diameter C15 = 3.5
  dimension "d387" diameter C16 = 7
  dimension "d388" distance P35 L50 = 0.5
  dimension "d389" distance P55 L49 = 2
  dimension "d390" distance L28 P87 = 3
  dimension "d403" distance L27 L51 = 10
  dimension "d442" diameter C26 = 33
  dimension "d443" distance P100 P101 = 0.25
  dimension "d444" distance P65 L55 = 26.9
extrude "Extrude7" cut sketch "Fan Face" profile of C1 C3 to an object
extrude "Extrude8" cut sketch "Fan Face" profile of C1 C2 C3 C4 to an object
chamfer "Chamfer4" distance 2.5
sketch "Lower Face" plane through (0, 0, -33) normal (0, 0, -1) x axis (1, 0, 0)
  line L1 (-20, 22.65) -> (20, 22.65)
  line L2 (-20, 0.25) -> (-20, 22.65)
  line L3 (-11.2472, 0.25) -> (-20, 0.25)
  line L4 (20, 0.25) -> (11.2472, 0.25)
  line L5 (20, 22.65) -> (20, 0.25)
  line L6 (-11.5806, -14.75) -> (-11.2472, 0.25)
  line L7 (-20, -14.75) -> (-11.5806, -14.75)
  line L8 (-20, 0.25) -> (-20, -14.75)
  line L9 (11.5806, -14.75) -> (11.2472, 0.25)
  line L10 (20, -14.75) -> (11.5806, -14.75)
  line L11 (20, 0.25) -> (20, -14.75)
  line L12 (-14.75, -14.75) -> (-14.75, 0)
  line L13 (14.75, -14.75) -> (14.75, 0)
  line L14 (14, 16) -> (11.0708, 2)
  line L15 (-14, 16) -> (14, 16)
  line L16 (-14, 16) -> (-11.0708, 2)
  line L17 (0, 0) -> (0, 16)
  arc A1 centre (0, 0) radius 11.25 clockwise from (-11.2472, 0.25) to (11.2472, 0.25)
  arc A2 centre (0, 0) radius 14.75 clockwise from (-14.75, 0) to (14.75, 0)
  point P5 (-11.2472, 0.25)
  point P9 (-11.2472, 0.25)
  point P4 (-20, 0.25)
  point P12 (-20, 0.25)
  point P6 (11.2472, 0.25)
  point P13 (11.2472, 0.25)
  point P8 (20, 0.25)
  point P16 (20, 0.25)
  point P10 (-11.5806, -14.75)
  point P7 (0, 0)
  point P17 (0, 0)
  point P20 (-14.75, -14.75)
  point P21 (14.75, -14.75)
  point P22 (11.0708, 2)
  point P25 (-11.0708, 2)
  point P26 (0, 16)
  point P27 (0, 0)
  point P19 (-14.75, 0)
  point P28 (-14.75, 0)
  point P11 (-20, -14.75)
  point P23 (14, 16)
  point P24 (-14, 16)
  coincident P5 P9
  tangent A1 L6
  coincident P4 P12
  vertical L8
  horizontal L7
  coincident P6 P13
  tangent A1 L9
  parallel L4 L10
  perpendicular L10 L11
  coincident P8 P16
  coincident P10 L10
  coincident P7 P17
  coincident L7 P20
  tangent A2 L12
  tangent A2 L13
  coincident L10 P21
  coincident A1 P22
  horizontal L15
  coincident A1 P25
  midpoint L15 P26
  coincident P17 P27
  vertical L17
  vertical L12
  coincident P19 P28
  vertical L13
  dimension "d90" distance P11 P12 = 15
  dimension "d93" distance A1 A2 = 3.5
  dimension "d97" distance P17 P22 = 2
  dimension "d98" distance P17 P25 = 2 (= "d97")
  dimension "d99" distance P26 P27 = 16
  dimension "d100" distance P23 P24 = 28
  dimension "d318" distance L8 P20 = 5.25
extrude "Extrude9" add sketch "Lower Face" profile of L3 L4 L6 L7 L8 L9 L10 L11 to an object offset -1
extrude "Extrude10" add sketch "Lower Face" profile of L1 L2 L3 L4 L5 L7 L8 L10 L11 A2 L12 L13 to an object
extrude "Extrude11" cut sketch "Lower Face" profile of A1 A2 L14 L15 L16 to an object offset 2 from offset -2
extrude "Extrude12" cut sketch "Fan Face" profile of L4 C10 to an object
fillet "Fillet3" radius 8
fillet "Fillet4" radius 5
extrude "Extrude13" cut sketch "Fan Face" profile of C6 C7 C8 C9 against normal blind 12
chamfer "Chamfer5" distance 1
fillet "Fillet5" radius 3
extrude "Extrude28" sketch "Fan Face" profile of L3 L13 L19 L20 L21 L22 L23 L25 L26 L27 L28 L34 L36 to an object
extrude "Extrude29" sketch "Fan Face" profile of L3 L13 L19 L20 L21 L22 L23 L25 L26 L27 L28 L30 L31 L32 L33 L34 L36 L37 L38 L39 to an object
extrude "Extrude30" sketch "Fan Face" profile of L21 L27 L28 L30 L34 blind 2.5
extrude "Extrude31" sketch "Fan Face" profile of L3 L12 L20 L21 L22 L24 L25 L28 L29 L34 L50 L51 blind 7
extrude "Extrude33" add sketch "Fan Face" profile of L20 L22 L24 L29 against normal blind 12.5
extrude "Extrude32" add sketch "Fan Face" profile of L3 L12 L20 L21 L25 L26 L27 L28 L29 L34 L37 C17 C18 C20 C21 L51 C23 C24 L52 L53 L54 against normal blind 5
fillet "Fillet18" radius 10
fillet "Fillet29" radius 4
fillet "Fillet15" radius 12
fillet "Fillet16" radius 25.5
fillet "Fillet17" radius 8
extrude "Extrude35" add sketch "Fan Face" profile of L2 L33 L35 L38 L39 C12 C13 L43 L44 L45 L46 L47 C26 against normal blind 8
extrude "Extrude36" cut sketch "Fan Face" profile of L21 L26 C14 C17 C20 C23 against normal blind 10
extrude "Extrude37" new body sketch "Fan Face" profile of L21 L26 L27 L28 L31 L32 L33 L34 L37 L48 L49 C15 L50 C18 C21 L51 C24 L52 L53 L54 blind 20 from offset 0.1
extrude "Extrude38" add sketch "Fan Face" profile of L21 L27 L30 L31 L32 L33 L34 L48 L49 to an object from offset 15.1
extrude "Extrude39" sketch "Fan Face" profile of L21 L27 L30 L34 blind -1
fillet "Fillet19" radius 18.75
fillet "Fillet20" radius 3.25
fillet "Fillet21" radius 3.25
fillet "Fillet22" radius 8
fillet "Fillet23" radius 80
fillet "Fillet24" radius 24.5
fillet "Fillet25" radius 6.5
fillet "Fillet26" radius 3
fillet "Fillet27" radius 2
fillet "Fillet28" radius 1
extrude "Extrude40" add of existing geometry blind 4
fillet "Fillet30" ChordLen 7
component_insert "Component Insert18"
joint "Assemble17" alignAngle 180 alignOffsetX 0 alignOffsetY 0 alignOffsetZ 0
fillet "Fillet31" ChordLen 5
fillet "Fillet32" ChordLen 0.5
fillet "Fillet33" ChordLen 2
fillet "Fillet34" ChordLen 5
sketch "Sketch7" plane through (0, 14.75, 0) normal (0, 1, 0) x axis (-1, 0, 0)
  curve K1 (34.0514, -50) -> (35.6569, -48.8074)
  line L1 (43.7111, -22.1138) -> (35.6569, -48.8074)
  line L2 (20, -14.9595) -> (43.7111, -22.1138)
  line L3 (20, -5.5) -> (20, -14.9595)
  line L4 (11.5806, -5.5) -> (20, -5.5)
  line L5 (11.5806, -33) -> (11.5806, -5.5)
  line L6 (11.75, -33) -> (11.5806, -33)
  line L7 (14.75, -45.746) -> (14.75, -36)
  curve K2 (14.75, -45.746) -> (14.8794, -46.229)
  line L8 (16.9123, -49.75) -> (14.8794, -46.229)
  curve K3 (16.9123, -49.75) -> (17.3453, -50)
  line L9 (34.0514, -50) -> (17.3453, -50)
  line L10 (27.6093, -45) -> (14.75, -45)
  line L11 (38.7457, -38.5704) -> (27.6093, -45)
  line L12 (26.2695, -40) -> (14.75, -40)
  line L13 (40.8552, -31.5789) -> (26.2695, -40)
  line L14 (37.7927, -25.5512) -> (42.2667, -26.9011)
  line L15 (14.1978, -34.2655) -> (37.7927, -25.5512)
  arc A1 centre (11.75, -36) radius 3 clockwise from (11.75, -33) to (14.75, -36)
  circle C1 centre (32.6973, -46.5) radius 1.35
  circle C2 centre (32.6973, -46.5) radius 1.75
  circle C3 centre (18.25, -36.5) radius 1.35
  circle C4 centre (18.25, -36.5) radius 1.75
  circle C5 centre (37.9048, -29.2409) radius 1.35
  circle C6 centre (37.9048, -29.2409) radius 1.75
  circle C7 centre (37.9048, -29.2409) radius 3.5
  circle C8 centre (18.25, -36.5) radius 3.5
  circle C9 centre (32.6973, -46.5) radius 3.5
  point P16 (14.75, -45)
  point P18 (38.7457, -38.5704)
  point P19 (14.75, -40)
  point P21 (40.8552, -31.5789)
  point P31 (42.2667, -26.9011)
  point P33 (14.1978, -34.2655)
  point P15 (17.3453, -50)
  coincident L7 P16
  perpendicular L7 L10
  coincident L1 P18
  coincident L7 P19
  perpendicular L7 L12
  parallel L11 L13
  coincident L1 P21
  equal L10 L11
  concentric C1 C2
  concentric C3 C4
  concentric C5 C6
  equal C3 C5
  equal C1 C5
  equal C4 C6
  equal C2 C4
  concentric C6 C7
  concentric C3 C8
  concentric C2 C9
  equal C7 C8
  equal C8 C9
  tangent L7 C8
  tangent L12 C8
  tangent L1 C9
  tangent L9 C9
  tangent L13 C7
  tangent L1 C7
  coincident L1 P31
  perpendicular L1 L14
  coincident A1 P33
  tangent C8 L15
  tangent C7 L14
  tangent C7 L15
  dimension "d455" distance L11 L13 = 5
  dimension "d456" distance L10 L12 = 5 (= "d455")
  dimension "d457" distance P15 L10 = 5
  dimension "d458" angle L12 L13 = 30
  dimension "d459" diameter C5 = 2.7
  dimension "d460" diameter C6 = 3.5
  dimension "d461" diameter C7 = 7
extrude "Extrude41" cut sketch "Sketch7" profile of C1 C3 C5 against normal blind 8
chamfer "Chamfer12" distance 1.35
extrude "Extrude42" cut sketch "Sketch7" profile of L1 L7 L10 L11 L12 L13 against normal blind 5
extrude "Extrude43" cut sketch "Sketch7" profile of K1 L1 A1 L7 K2 L8 K3 L9 L10 L11 L12 L13 C1 C2 C3 C4 C5 C6 L14 L15 against normal blind 1
offset_faces "OffsetFaces1" distance -0.25
extrude "Extrude44" sketch "Sketch7" profile of K1 L1 A1 L7 K2 L8 K3 L9 L10 L11 L12 L13 C2 C4 C6 L14 L15 blind 2.5 from offset 0.1
chamfer "Chamfer13" distance 1.5
fillet "Fillet37" ChordLen 3
fillet "Fillet38" ChordLen 5
fillet "Fillet39" ChordLen 10
fillet "Fillet42" ChordLen 5
fillet "Fillet43" ChordLen 5
fillet "Fillet40" ChordLen 1.5
fillet "Fillet41" ChordLen 1
fillet "Fillet35" ChordLen 5
fillet "Fillet36" ChordLen 5
split "Split1"
mirror "Mirror1" mirrorStitchTolerance 0.1
mirror "Mirror2" mirrorStitchTolerance 0.1
component_insert "Component Insert21"
joint "Assemble20" alignAngle 0 alignOffsetX 0 alignOffsetY 0 alignOffsetZ 0
component_insert "Component Insert20"
joint "Assemble19" alignAngle 0 alignOffsetX 0 alignOffsetY 0 alignOffsetZ 0
component_insert "Component Insert19"
joint "Assemble18" alignAngle 0 alignOffsetX 0 alignOffsetY 0 alignOffsetZ 0
component_insert "Component Insert9"
joint "Assemble8" alignAngle 0 alignOffsetX 0 alignOffsetY 0 alignOffsetZ 0
component_insert "Component Insert7"
component_insert "Component Insert8"
joint "Assemble6" alignAngle 0 alignOffsetX 0 alignOffsetY 0 alignOffsetZ 0
joint "Assemble7" alignAngle 0 alignOffsetX 0 alignOffsetY 0 alignOffsetZ 0
component_insert "Component Insert10"
component_insert "Component Insert11"
component_insert "Component Insert12"
component_insert "Component Insert13"
joint "Assemble9" alignAngle 0 alignOffsetX 0 alignOffsetY 0 alignOffsetZ 0
joint "Assemble10" alignAngle 0 alignOffsetX 0 alignOffsetY 0 alignOffsetZ 0
joint "Assemble11" alignAngle 0 alignOffsetX 0 alignOffsetY 0 alignOffsetZ 0
joint "Assemble12" alignAngle 0 alignOffsetX 0 alignOffsetY 0 alignOffsetZ 0
sketch "Mount Face" plane through (0, 0, 0) normal (0, 1, 0) x axis (1, 0, 0)
  line L1 (-40, -28.3) -> (-15.5, -28.3)
  line L2 (-40, -40.3) -> (-40, -28.3)
  line L3 (-40, -2) -> (-40, -28.3)
  line L4 (-19, -2) -> (-40, -2)
  line L5 (-19, -24.8) -> (-19, -2)
  line L6 (-15.5, -28.3) -> (-19, -24.8)
  line L7 (-11.8, -32) -> (-15.5, -28.3)
  line L8 (31, -32) -> (-11.8, -32)
  line L9 (31, -40.8) -> (31, -32)
  line L10 (-25, -48) -> (-25, -8)
  line L11 (25, -38) -> (-25, -38)
  line L12 (-11.8, -40.3) -> (-11.8, -32)
  line L13 (-40, -54) -> (-40, -40.3)
  line L14 (31, -54) -> (-40, -54)
  line L15 (31, -40.8) -> (31, -54)
  line L16 (-40, -40.3) -> (-11.8, -40.3)
  line L17 (-19, -44) -> (31, -44)
  line L18 (-19, -54) -> (-19, -44)
  line L19 (-22, -15.8) -> (-19, -15.8)
  line L20 (-22, -2) -> (-22, -15.8)
  line L21 (-25, -8) -> (-35, -8)
  line L22 (-44, -2) -> (-40, -2)
  line L23 (-44, -54) -> (-44, -2)
  line L24 (-40, -54) -> (-44, -54)
  circle C1 centre (-25, -8) radius 2.75
  circle C2 centre (-25, -8) radius 5.5
  circle C3 centre (25, -38) radius 2.75
  circle C4 centre (25, -38) radius 5.5
  circle C5 centre (-25, -48) radius 2.75
  circle C6 centre (-25, -48) radius 5.5
  circle C7 centre (-35, -8) radius 2.75
  point P12 (-25, -8)
  point P14 (-25, -8)
  point P13 (25, -38)
  point P17 (25, -38)
  point P16 (-25, -38)
  point P10 (31, -40.8)
  point P22 (31, -40.8)
  point P15 (-25, -48)
  point P23 (-25, -48)
  point P25 (31, -44)
  point P27 (-19, -54)
  point P28 (-19, -15.8)
  point P30 (-22, -2)
  point P31 (-35, -8)
  point P32 (-35, -8)
  point P11 (-25, -8)
  point P33 (-25, -8)
  point P4 (-40, -40.3)
  point P36 (-40, -40.3)
  point P20 (-40, -54)
  point P37 (-40, -54)
  point P1 (0, 0)
  point P2 (-15.5, -28.3)
  point P3 (-40, -28.3)
  point P18 (25, -38)
  point P24 (-25, -48)
  point P6 (-19, -2)
  horizontal L1
  vertical L2
  perpendicular L1 L3
  perpendicular L2 L4
  perpendicular L1 L5
  parallel L6 L7
  parallel L1 L8
  perpendicular L1 L9
  concentric C1 C2
  coincident P12 P14
  coincident P13 P17
  perpendicular L9 L11
  vertical L10
  equal C1 C3
  concentric C3 C4
  equal C2 C4
  coincident L10 P16
  perpendicular L13 L14
  perpendicular L14 L15
  coincident P10 P22
  coincident P15 P23
  concentric C5 C6
  equal C1 C5
  equal C2 C6
  perpendicular L13 L16
  horizontal L16
  vertical L12
  coincident L15 P25
  perpendicular L15 L17
  coincident L14 P27
  perpendicular L14 L18
  coincident L5 P28
  perpendicular L5 L19
  coincident L4 P30
  perpendicular L4 L20
  equal C1 C7
  coincident P31 P32
  coincident P11 P33
  horizontal L21
  perpendicular L3 L22
  perpendicular L22 L23
  coincident P4 P36
  perpendicular L23 L24
  coincident P20 P37
  dimension "d138" distance P1 L2 = 40
  dimension "d139" distance P1 L5 = 19
  dimension "d140" angle L1 L6 = 45
  dimension "d141" distance P1 L1 = 28.3
  dimension "d142" distance P2 L8 = 3.7
  dimension "d143" distance P2 P3 = 24.5
  dimension "d144" distance P3 P4 = 12
  dimension "d146" distance P1 P11 = 25
  dimension "d147" diameter C2 = 11
  dimension "d148" diameter C1 = 5.5
  dimension "d150" distance L4 P12 = 6 (= "d168")
  dimension "d154" distance L9 P18 = 6 (= "d168")
  dimension "d155" distance P16 P17 = 50
  dimension "d156" distance P11 P15 = 40
  dimension "d157" distance P11 P16 = 30
  dimension "d159" distance L14 P24 = 6 (= "d168")
  dimension "d167" distance P1 P18 = 38
  dimension "d168" distance L8 P18 = 6
  dimension "d169" distance L5 P11 = 6 (= "d168")
  dimension "d180" distance P18 L17 = 6 (= "d168")
  dimension "d181" distance P24 L18 = 6 (= "d168")
  dimension "d193" distance P6 L20 = 3
  dimension "d194" distance P3 L19 = 12.5
  dimension "d196" distance P32 P33 = 10
  dimension "d197" distance P31 L23 = 9
extrude "Extrude14" sketch "Mount Face" profile of L1 L2 L7 L12 L16 to an object offset 0.25
extrude "Extrude15" sketch "Mount Face" profile of L1 L2 L3 L4 L5 L6 L7 L8 L9 C3 L12 L13 L14 L15 C5 L16 L17 L18 L19 L20 C7 L22 L23 L24 blind 8.65
chamfer "Chamfer6" distance 2.5
sketch "Sketch5" plane through (0, 0, 40.3) normal (0, 0, 1) x axis (-1, 0, 0)
  line L1 (40, -16.6) -> (11.8, -16.6)
  line L2 (40, -3.65) -> (40, -16.6)
  line L3 (11.8, -3.65) -> (40, -3.65)
  line L4 (11.8, -16.6) -> (11.8, -3.65)
  line L5 (11.8, -10) -> (40, -10)
  circle C1 centre (35, -10) radius 2.625
  circle C2 centre (20, -10) radius 2.625
  point P6 (40, -10)
  point P7 (11.8, -10)
  point P8 (35, -10)
  point P9 (20, -10)
  point P4 (40, -3.65)
  coincident L2 P6
  coincident L4 P7
  perpendicular L4 L5
  coincident L5 P8
  coincident L5 P9
  equal C1 C2
  dimension "d171" distance P4 P6 = 6.35 (= "( 12.7 / 2 ) * 1 mm")
  dimension "d172" diameter C1 = 5.25
  dimension "d173" distance P6 P8 = 5
  dimension "d174" distance P8 P9 = 15
extrude "Extrude16" cut sketch "Sketch5" profile of C1 C2 to an object
chamfer "Chamfer7" distance 2.5
fillet "Fillet7" radius 2
fillet "Fillet8" radius 4
fillet "Fillet9" radius 4
fillet "Fillet10" radius 2
fillet "Fillet11" radius 4
fillet "Fillet12" radius 1
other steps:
joint_origin "JointOrigin1"
joint_origin "JointOrigin8"
joint_origin "JointOrigin9"
joint_origin "JointOrigin10"
joint_origin "JointOrigin11"
joint_origin "JointOrigin12"
joint_origin "JointOrigin13"
joint_origin "JointOrigin22"
joint_origin "JointOrigin24"
joint_origin "JointOrigin25"

design "HW_M5x10-BHCS"
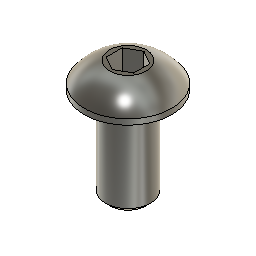
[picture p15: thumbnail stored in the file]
